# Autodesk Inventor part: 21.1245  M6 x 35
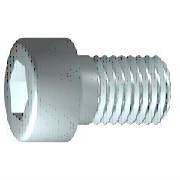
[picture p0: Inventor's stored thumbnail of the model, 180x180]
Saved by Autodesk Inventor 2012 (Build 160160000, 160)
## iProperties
Created: 2006-02
Part Number: 21.1245  M6 x 35
Material: Steel, Mild
Description: Cylinder Head Cap Screw
Document SubType Name: Modeling
Standard: DIN 7984
Designer: Andy Moles
Standards Organization: DIN
Language: en-US
Size Designation: M6 x 35
Categories: <MemberInstance><Categories><Category DisplayName="Fasteners" InternalName="e4da775c-781d-43d5-af7c-5136215cf5a6" Mnemonic="FSTN"><Category DisplayName="Bolts"
Density: 7.86 g/cm^3
Mass: 9.81936 g
Surface Area: 9.72304 cm^2
Volume: 1.24928 cm^3
Author: Andy Moles
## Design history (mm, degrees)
body "Solid1"
workplane "Work Plane1"
revolve "Body" stored, may be unused: angle "d10" = 90 deg
sketch "Sketch2"
  geometry: L1 (0, -6)-(0, 8) reference; L2 (-6, 0)-(8, 0) reference; L3 (2.309, 0)-(1.155, -2); L4 (1.155, -2)-(-1.155, -2); L5 (-1.155, -2)-(-2.309, 0); L6 (-2.309, 0)-(-1.155, 2); L7 (-1.155, 2)-(1.155, 2); L8 (1.155, 2)-(2.309, 0); 2 further points
  constraints: 12 end point, 1 coincident, 1 horizontal alignment, 1 point on line, 12 other
extrude "Slot" join sketch "Sketch2" stored distance "d11" = 10; taper "d12" = 0 deg
fillet "Fillet1" dims "d17" = 0.6 (= RR)
feature "Thread" dims "d13" = 18 (= GEL), "d14" = 0
chamfer "Chamfer1" distance "d15" = 0.61345 (= -0.5 x SPD + 0.5 x GD); stored, may be unused: second distance "d16" = 0.61345 (= GUL), angle "d27" = 45 deg
sketch "Sketch1"
  geometry: L1 (0.333, 0)-(35, 0); L2 (35, 0)-(35, 3); L3 (35, 3)-(17, 3); L4 (17, 3)-(16.386, 3); L5 (16.386, 3)-(0, 3); L6 (0, 3)-(0, 5); L7 (0, 5)-(-4, 5); L8 (-4, 5)-(-4, 2.309); L9 (-4, 2.309)-(-1, 2.309); L10 (-1, 2.309)-(0.333, 0); L11 (-7.9, 0)-(46.7, 0) reference; L12 (0, -0.5)-(0, 6.5) reference; L13 (17, 3)-(0, 3)
  constraints: 22 end point, 6 parallel, 2 collinear, 2 perpendicular, 1 horizontal, 1 midpoint
  dimensions: "d1" = 18 distance from line of L3.end L2 (= GEL); "d2" = 0.61355 distance of L4.end L3.end (computed from GAL); "d3" = 4 distance between parallel lines of L8 L6 (= KOH); "d4" = 3 distance of L8.end L9.end (= INTI); "d5" = 60 deg angle of L10 L1; "d6" = 6 diameter of L3 L1 (= GD); "d7" = 6 diameter of L5 L1 (= BDM); "d8" = 4.6188 diameter of L9 L1 (= 1.1547 x SW); "d9" = 10 diameter of L7 L1 (= KOD); "d26" = 35 distance between parallel lines of L12 L2 (= NLG)
other parameters: "GD" = 6 (= NND) [user parameter; used in 2 equation terms], "NLG" = 35 [user parameter; used in 1 equation term], "GEL" = 18 [user parameter; used in 2 equation terms], "KOD" = 10 [user parameter; used in 1 equation term], "KOH" = 4 [user parameter; used in 1 equation term], "INTI" = 3 [user parameter; used in 1 equation term], "GAL" = 0.61345 (= 0.61345 x PTC) [user parameter; used in 1 equation term], "GUL" = 0.61345 (= 0.61345 x PTC) [user parameter; used in 1 equation term], "BDM" = 6 (= NND) [user parameter; used in 1 equation term], "SW" = 4 [user parameter; used in 2 equation terms], "RR" = 0.6 [user parameter; used in 1 equation term], "SPD" = 4.7731 (= NND - 1.2269 x PTC) [user parameter; used in 1 equation term], "d19" = 0, "d28" = 0, "d29" = 0, "TOA" = 30 deg [user parameter], "GD1" = 4.7731 (= THREADDIA - 1.2269 x PTC) [user parameter], "THREADDIA" = 6 [user parameter; used in 1 equation term], "FAWI" = 45 deg [user parameter], "ANG" = 120 deg [user parameter], "PTC" = 1 [user parameter; used in 5 equation terms], "NND" = 6 [user parameter; used in 3 equation terms], "E0" = 4.62 (= 1.155 x SW) [user parameter]
